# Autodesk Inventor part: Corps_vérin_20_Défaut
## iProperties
Shininess: 64.0
Length Units: 11269
Angle Units: 11279
Time Units: 11290
Mass Units: 11283
Length Display Precision: 3
Angle Display Precision: 2
Compacted: True
Part Number: Corps_vérin_20_Défaut
Document SubType Name: Modeling
Created: 2006-01
Material: Par défaut
Designer: riri
Density: 0.0
Volumn: 0.0
Area: 0.0
PropertySet Name: Model Information
Control State: 0
Master: False
Checked Out: False
Author: riri
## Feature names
1. Base1
